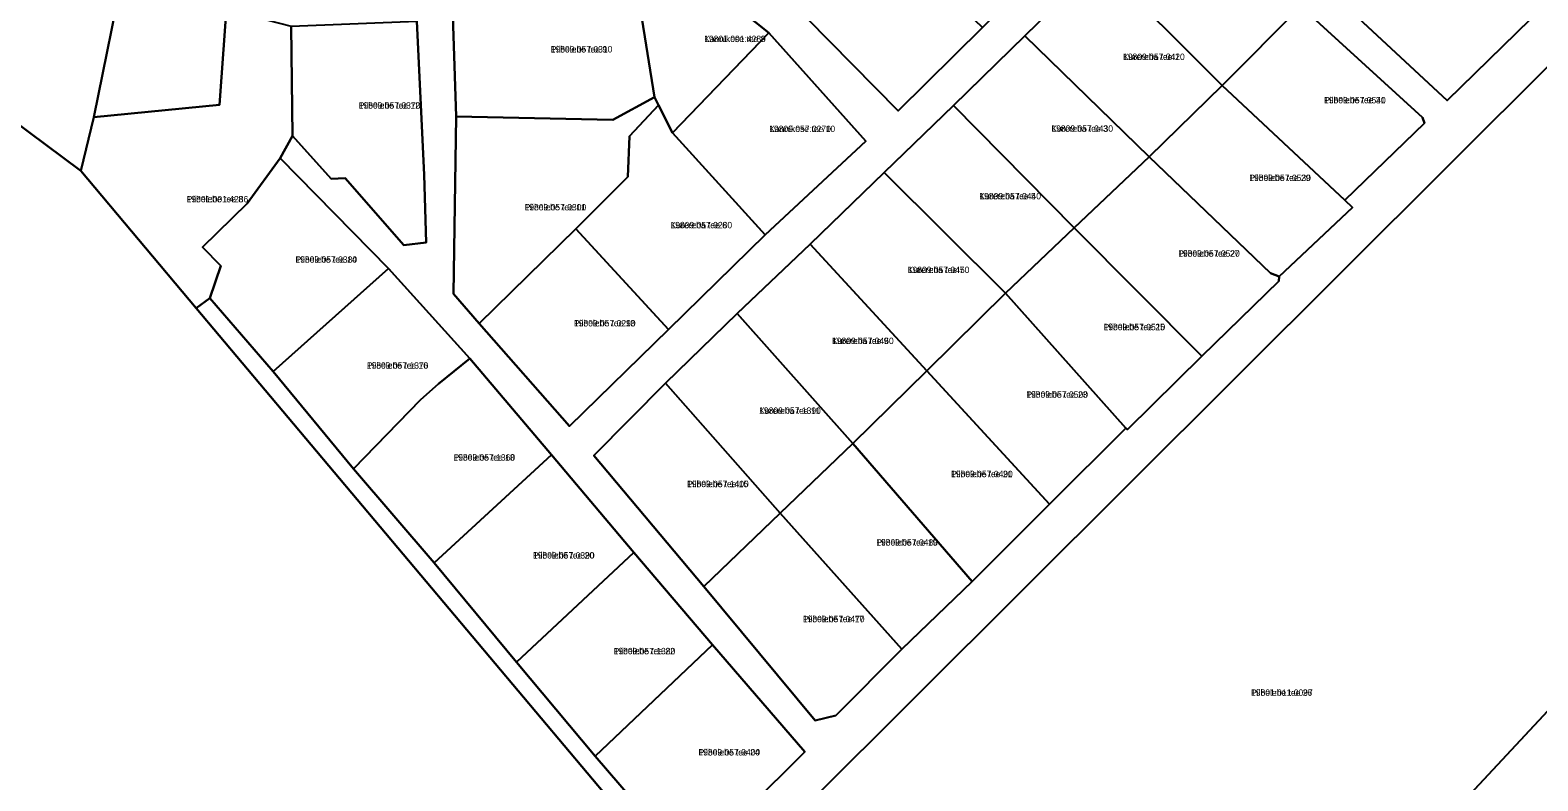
# Model space of a CAD drawing. Extents: x 516875 to 535633, y 6574491 to 6593094.
# Drawn here: x 521454.9 to 521809.5, y 6587475.1 to 6587651.6 of the extents above; entities that cross this region are included whole.
import ezdxf

# ---------------------------------------------------------------- set-up
doc = ezdxf.new("R2010")
doc.units = 0
for name, color, linetype in [('L_AADRESS', 7, 'Continuous'), ('PIIR', 7, 'Continuous'), ('TUNNUS', 7, 'Continuous')]:
    doc.layers.add(name, color=color, linetype=linetype)

msp = doc.modelspace()

# ---------------------------------------------------------------- linework, layer by layer
at = {"layer": 'PIIR'}
for points in [[(521625.96, 6587776.49), (521596.72, 6587802.09), (521579.05, 6587782.09), (521564.23, 6587763.63), (521565.17, 6587759.77), (521595.61, 6587736.25), (521600.16, 6587724.96), (521605.12, 6587694.55), (521606.11, 6587688.7), (521632.22, 6587659.91), (521659.03, 6587632.59), (521678.9, 6587652.2), (521696.92, 6587669.98), (521714.72, 6587688.83), (521713.41, 6587692.29), (521688.86, 6587715.51), (521666.4, 6587737.27), (521645.83, 6587757.13)], [(521614.16, 6587662.53), (521608.15, 6587661.76), (521599.03, 6587683.98), (521596.22, 6587692.38), (521593.67, 6587692.32), (521594.65, 6587721.9), (521594.43, 6587724.85), (521591.92, 6587731.78), (521559.21, 6587757.32), (521550.74, 6587746.78), (521551.76, 6587723.04), (521552.9, 6587692.41), (521554.14, 6587662.15), (521555.11, 6587631.28), (521554.53, 6587589.6), (521560.56, 6587582.59), (521581.8, 6587558.44), (521605.07, 6587581.18), (521627.8, 6587603.47), (521651.46, 6587625.46), (521628.67, 6587650.99)], [(521493.95, 6587689.74), (521507.66, 6587708.62), (521515, 6587705.75), (521510.49, 6587654.01), (521516.32, 6587652.53), (521516.62, 6587626.73), (521513.71, 6587621.48), (521505.97, 6587610.8), (521495.47, 6587600.56), (521499.76, 6587596.15), (521497.2, 6587588.61), (521494, 6587586.23), (521466.85, 6587618.54), (521469.89, 6587631.13), (521499.45, 6587634.07), (521503.2, 6587686.17)], [(521455.99, 6587689.7), (521462.55, 6587693.47), (521478.18, 6587693.28), (521490.98, 6587685.72), (521477.23, 6587667.12), (521469.89, 6587631.13), (521466.85, 6587618.54), (521426.52, 6587648.56)], [(521477.23, 6587667.12), (521490.98, 6587685.72), (521493.95, 6587689.74), (521503.2, 6587686.17), (521499.45, 6587634.07), (521469.89, 6587631.13)], [(521723.61, 6587684.04), (521753.77, 6587657.16), (521735.24, 6587638.59), (521706.43, 6587667.41)], [(521764.04, 6587657.46), (521788.76, 6587683.12), (521814.3, 6587660.64), (521788.16, 6587635.09)], [(521651.36, 6587678.66), (521678.9, 6587652.2), (521659.03, 6587632.59), (521632.22, 6587659.91)], [(521706.43, 6587667.41), (521735.24, 6587638.59), (521718.06, 6587621.77), (521688.87, 6587650.26)], [(521554.14, 6587662.15), (521598.23, 6587660.43), (521598.45, 6587656.37), (521601.8, 6587635.84), (521591.94, 6587630.53), (521555.11, 6587631.28)], [(521598.45, 6587656.37), (521598.23, 6587660.43), (521608.15, 6587661.76), (521614.16, 6587662.53), (521628.67, 6587650.99), (521606.03, 6587627.42), (521602.67, 6587633.93), (521601.8, 6587635.84)], [(521753.77, 6587657.16), (521782.41, 6587631.03), (521782.81, 6587629.71), (521764.11, 6587611.62), (521735.24, 6587638.59)], [(521525.74, 6587616.61), (521516.62, 6587626.73), (521516.32, 6587652.53), (521545.84, 6587653.67), (521547.61, 6587617.59), (521548.1, 6587601.65), (521542.84, 6587601.01), (521529.03, 6587616.76)], [(521606.03, 6587627.42), (521628.67, 6587650.99), (521651.46, 6587625.46), (521627.8, 6587603.47)], [(521688.87, 6587650.26), (521718.06, 6587621.77), (521700.49, 6587605.13), (521672.09, 6587633.9)], [(521827.35, 6587635.21), (521841.86, 6587608.63), (521853.18, 6587587.99), (521865.17, 6587566.11), (521871.16, 6587555.15), (521687.87, 6587358.55), (521612.94, 6587444.85), (521813.65, 6587644.82)], [(521735.24, 6587638.59), (521764.11, 6587611.62), (521765.92, 6587609.91), (521748.67, 6587593.67), (521746.66, 6587594.47), (521718.06, 6587621.77)], [(521554.53, 6587589.6), (521555.11, 6587631.28), (521591.94, 6587630.53), (521601.8, 6587635.84), (521602.67, 6587633.93), (521595.91, 6587626.7), (521595.46, 6587617.09), (521583.25, 6587604.85), (521560.56, 6587582.59)], [(521595.46, 6587617.09), (521595.91, 6587626.7), (521602.67, 6587633.93), (521606.03, 6587627.42), (521627.8, 6587603.47), (521605.07, 6587581.18), (521583.25, 6587604.85)], [(521672.09, 6587633.9), (521700.49, 6587605.13), (521684.27, 6587589.77), (521655.81, 6587618.09)], [(521497.2, 6587588.61), (521499.76, 6587596.15), (521495.47, 6587600.56), (521505.97, 6587610.8), (521513.71, 6587621.48), (521539.19, 6587595.56), (521512.09, 6587571.34)], [(521718.06, 6587621.77), (521746.66, 6587594.47), (521748.67, 6587593.67), (521748.6, 6587592.61), (521730.47, 6587574.9), (521700.49, 6587605.13)], [(521655.81, 6587618.09), (521684.27, 6587589.77), (521665.81, 6587571.47), (521638.37, 6587601.28)], [(521560.56, 6587582.59), (521583.25, 6587604.85), (521605.07, 6587581.18), (521581.8, 6587558.44)], [(521700.49, 6587605.13), (521730.47, 6587574.9), (521713, 6587557.68), (521712.58, 6587558.04), (521684.27, 6587589.77)], [(521638.37, 6587601.28), (521665.81, 6587571.47), (521648.39, 6587554.4), (521621.2, 6587584.98)], [(521512.09, 6587571.34), (521539.19, 6587595.56), (521558.33, 6587574.39), (521550.95, 6587568.41), (521546.73, 6587564.7), (521530.98, 6587548.45)], [(521684.27, 6587589.77), (521712.58, 6587558.04), (521694.65, 6587540.15), (521665.81, 6587571.47)], [(521621.2, 6587584.98), (521648.39, 6587554.4), (521631.33, 6587538), (521604.37, 6587568.55)], [(521530.98, 6587548.45), (521546.73, 6587564.7), (521550.95, 6587568.41), (521558.33, 6587574.39), (521577.57, 6587551.7), (521549.93, 6587526.36)], [(521665.81, 6587571.47), (521694.65, 6587540.15), (521676.5, 6587521.95), (521648.39, 6587554.4)], [(521604.37, 6587568.55), (521631.33, 6587538), (521613.38, 6587520.74), (521587.53, 6587551.57)], [(521687.87, 6587358.55), (521871.16, 6587555.15), (521876.3, 6587545.74), (521888.3, 6587523.62), (521900.33, 6587501.92), (521909.85, 6587484.57), (521917.9, 6587475.4), (521946.92, 6587442.06), (521972.62, 6587418.33), (521806.9, 6587220.36), (521761.42, 6587272.68)], [(521549.93, 6587526.36), (521577.57, 6587551.7), (521596.89, 6587528.79), (521569.29, 6587503)], [(521648.39, 6587554.4), (521676.5, 6587521.95), (521659.93, 6587506.05), (521631.33, 6587538)], [(521631.33, 6587538), (521659.93, 6587506.05), (521644.44, 6587490.44), (521639.51, 6587489.27), (521613.38, 6587520.74)], [(521569.29, 6587503), (521596.89, 6587528.79), (521615.38, 6587507.06), (521587.8, 6587480.89)], [(521615.38, 6587507.06), (521637.09, 6587481.89), (521610.06, 6587455.03), (521587.8, 6587480.89)]]:
    msp.add_lwpolyline(points, close=True, dxfattribs=at)
for points in [[(521321.81, 6587470.42), (521323.19, 6587480.09), (521321.45, 6587484.64), (521307.81, 6587497.68), (521267.05, 6587518.5), (521260.71, 6587524.03), (521258.87, 6587562.81), (521273.53, 6587582.85), (521290.9, 6587610.86), (521303.54, 6587638.57), (521332.32, 6587670.88), (521353.41, 6587696.37), (521383.82, 6587678.95), (521403.29, 6587665.06), (521426.52, 6587648.56), (521466.85, 6587618.54), (521494, 6587586.23), (521612.94, 6587444.85)], [(521706.43, 6587667.41), (521688.87, 6587650.26), (521672.09, 6587633.9), (521655.81, 6587618.09), (521638.37, 6587601.28), (521621.2, 6587584.98), (521604.37, 6587568.55), (521587.53, 6587551.57), (521613.38, 6587520.74), (521639.51, 6587489.27), (521644.44, 6587490.44), (521659.93, 6587506.05), (521676.5, 6587521.95), (521694.65, 6587540.15), (521712.58, 6587558.04), (521713, 6587557.68), (521730.47, 6587574.9), (521748.6, 6587592.61), (521748.67, 6587593.67), (521765.92, 6587609.91), (521764.11, 6587611.62), (521782.81, 6587629.71), (521782.41, 6587631.03), (521753.77, 6587657.16)], [(521764.04, 6587657.46), (521788.16, 6587635.09), (521814.3, 6587660.64)], [(521813.65, 6587644.82), (521612.94, 6587444.85), (521494, 6587586.23), (521497.2, 6587588.61), (521512.09, 6587571.34), (521530.98, 6587548.45), (521549.93, 6587526.36), (521569.29, 6587503), (521587.8, 6587480.89), (521610.06, 6587455.03), (521637.09, 6587481.89), (521615.38, 6587507.06), (521596.89, 6587528.79), (521577.57, 6587551.7), (521558.33, 6587574.39), (521539.19, 6587595.56), (521513.71, 6587621.48), (521516.62, 6587626.73), (521525.74, 6587616.61), (521529.03, 6587616.76), (521542.84, 6587601.01), (521548.1, 6587601.65), (521547.61, 6587617.59), (521545.84, 6587653.67)]]:
    msp.add_lwpolyline(points, dxfattribs=at)

# ---------------------------------------------------------------- texts
at = {"layer": 'L_AADRESS'}
for s, p in [('Piibelehe tee 9', (521577.36, 6587646.34)), ('Kannikese tee 8', (521613.45, 6587648.79)), ('Kurereha tee 1', (521711.96, 6587644.59)), ('Piibelehe tee 12', (521532.21, 6587633.14)), ('Piibelehe tee 31', (521759.23, 6587634.39)), ('Kannikese tee 10', (521628.75, 6587627.63)), ('Kurereha tee 3', (521695.1, 6587627.7)), ('Piibelehe tee 29', (521741.63, 6587616.13)), ('Piibelehe tee 8', (521491.73, 6587611.11)), ('Kurereha tee 5', (521678.15, 6587611.81)), ('Piibelehe tee 11', (521571.2, 6587609.21)), ('Kurereha tee 6', (521605.52, 6587605.01)), ('Piibelehe tee 14', (521517.33, 6587596.91)), ('Piibelehe tee 27', (521724.92, 6587598.33)), ('Kurereha tee 7', (521661.32, 6587594.48)), ('Piibelehe tee 13', (521582.82, 6587581.93)), ('Piibelehe tee 25', (521707.37, 6587581.04)), ('Kurereha tee 9', (521643.51, 6587577.8)), ('Piibelehe tee 16', (521534.11, 6587572)), ('Piibelehe tee 23', (521689.2, 6587565.16)), ('Kurereha tee 11', (521626.38, 6587561.38)), ('Piibelehe tee 18', (521554.49, 6587550.38)), ('Piibelehe tee 21', (521671.52, 6587546.48)), ('Piibelehe tee 15', (521609.43, 6587544.13)), ('Piibelehe tee 19', (521653.91, 6587530.4)), ('Piibelehe tee 20', (521573.18, 6587527.35)), ('Piibelehe tee 17', (521636.66, 6587512.38)), ('Piibelehe tee 22', (521592.15, 6587504.84)), ('Piibelehe tee 26', (521742.05, 6587495.07)), ('Piibelehe tee 24', (521612.1, 6587481.04))]:
    msp.add_text(s, height=1.5, dxfattribs=at).set_placement(p)
at = {"layer": 'TUNNUS'}
for s, p in [('19809:057:0310', (521577.36, 6587646.34)), ('19801:001:4289', (521613.45, 6587648.79)), ('19809:057:0420', (521711.96, 6587644.59)), ('19809:057:0370', (521532.21, 6587633.14)), ('19809:057:0540', (521759.23, 6587634.39)), ('19809:057:0270', (521628.75, 6587627.63)), ('19809:057:0430', (521695.1, 6587627.7)), ('19809:057:0530', (521741.63, 6587616.13)), ('19801:001:4286', (521491.73, 6587611.11)), ('19809:057:0440', (521678.15, 6587611.81)), ('19809:057:0300', (521571.2, 6587609.21)), ('19809:057:0280', (521605.52, 6587605.01)), ('19809:057:0380', (521517.33, 6587596.91)), ('19809:057:0520', (521724.92, 6587598.33)), ('19809:057:0450', (521661.32, 6587594.48)), ('19809:057:0290', (521582.82, 6587581.93)), ('19809:057:0510', (521707.37, 6587581.04)), ('19809:057:0460', (521643.51, 6587577.8)), ('19809:057:1370', (521534.11, 6587572)), ('19809:057:0500', (521689.2, 6587565.16)), ('19809:057:1390', (521626.38, 6587561.38)), ('19809:057:1360', (521554.49, 6587550.38)), ('19809:057:0490', (521671.52, 6587546.48)), ('19809:057:1400', (521609.43, 6587544.13)), ('19809:057:0480', (521653.91, 6587530.4)), ('19809:057:0390', (521573.18, 6587527.35)), ('19809:057:0470', (521636.66, 6587512.38)), ('19809:057:1380', (521592.15, 6587504.84)), ('19801:011:0097', (521742.05, 6587495.07)), ('19809:057:0400', (521612.1, 6587481.04))]:
    msp.add_text(s, height=1.5, dxfattribs=at).set_placement(p)

doc.saveas('drawing.dxf')
